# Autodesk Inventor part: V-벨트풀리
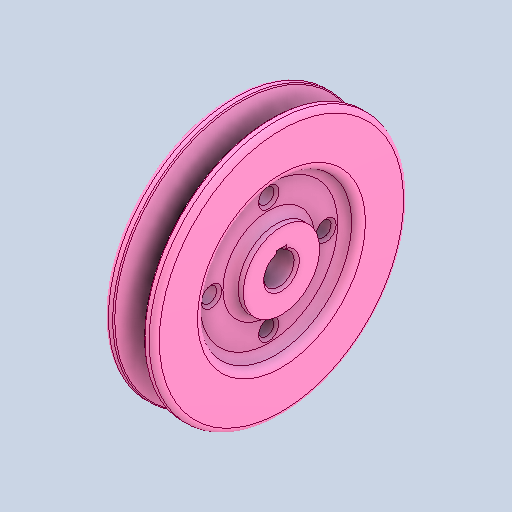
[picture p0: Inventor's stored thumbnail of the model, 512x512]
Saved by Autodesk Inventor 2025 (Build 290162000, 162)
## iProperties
Created: 2025-08
Part Number: V-벨트풀리
Material: 강철, 연강
Document SubType Name: Modeling
Designer: infra028
Density: 7.86 g/cm^3
Appearance: 기본값
Author: jhkim
Sending System: Autodesk Inventor 2026
Preprocessor: ST-DEVELOPER v20.1
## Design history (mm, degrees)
feature "솔리드1"
node "솔리드2"
